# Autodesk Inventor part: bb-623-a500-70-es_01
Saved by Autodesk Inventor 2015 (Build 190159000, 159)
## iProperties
Created: 2022-04
Part Number: bb-623-a500-70-es_01
Checked By: TraceParts S.A.
Material: Generic
Catalog Web Link: www.traceparts.com
Document SubType Name: Modeling
Designer: TraceParts
Density: 1 g/cm^3
Appearance: Default
Company: TraceParts S.A.
Author: TraceParts
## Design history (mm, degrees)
feature "bb-623-a500-70-es_01.ipt"
body "Solid1"
